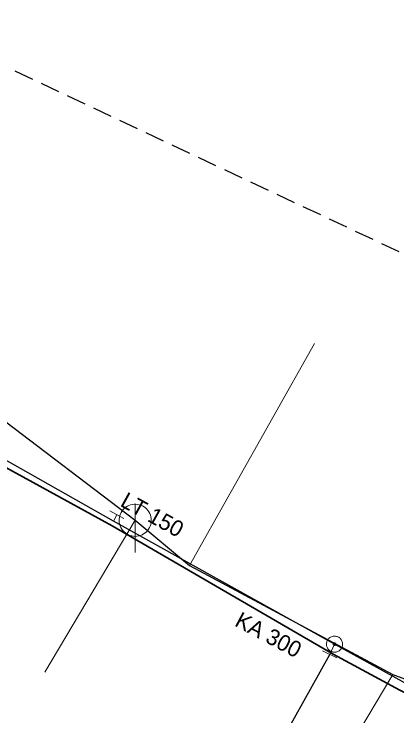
# Model space of a CAD drawing. Extents: x -749365 to -748625, y -965388 to -964881.
# Drawn here: x -749326.21 to -749302.39, y -964927.15 to -964883.5 of the extents above; entities that cross this region are included whole.
import ezdxf

# ---------------------------------------------------------------- set-up
doc = ezdxf.new("R2010")
doc.units = 0
doc.header["$LTSCALE"] = 0.4
doc.linetypes.add('MEDIUM_DASHED', pattern=[4.5, 3, -1.5])
for name, color, linetype, lineweight in [('1', 7, 'MEDIUM_DASHED', 25), ('11', 7, 'Continuous', 13), ('14', 7, 'Continuous', 13), ('17', 7, 'Continuous', 25), ('22', 7, 'Continuous', 13), ('34', 7, 'Continuous', 13), ('47', 7, 'Continuous', 13)]:
    doc.layers.add(name, color=color, linetype=linetype, lineweight=lineweight)

msp = doc.modelspace()

# ---------------------------------------------------------------- linework, layer by layer
at = {"layer": '1'}
msp.add_lwpolyline([(-748913.896, -965162.751), (-749358.2, -964911.234), (-749358.98, -964910.689), (-749359.642, -964910.006), (-749360.163, -964909.209), (-749360.523, -964908.329), (-749360.711, -964907.396), (-749360.718, -964906.445), (-749360.545, -964905.509), (-749360.198, -964904.624), (-749359.689, -964903.82), (-749359.037, -964903.126), (-749338.098, -964884.732), (-749337.314, -964884.168), (-749336.437, -964883.765), (-749335.498, -964883.538), (-749334.533, -964883.496), (-749333.578, -964883.64), (-749332.669, -964883.965), (-749106.184, -964990.559)], dxfattribs=at)
at = {"layer": '11'}
for p, q in [((-749307.528, -964903.991), (-749315.285, -964917.793)), ((-749324.298, -964924.421), (-749318.67, -964914.98)), ((-749313.264, -964942.418), (-749302.649, -964924.581))]:
    msp.add_line(p, q, dxfattribs=at)
at = {"layer": '14', "lineweight": 25}
msp.add_line((-749340.739, -964898.23), (-749318.67, -964914.98), dxfattribs=at)
at = {"layer": '14'}
for p, q in [((-749320.025, -964915.03), (-749319.813, -964914.633)), ((-749306.274, -964922.687), (-749306.572, -964923.32))]:
    msp.add_line(p, q, dxfattribs=at)
at = {"layer": '14', "lineweight": 25}
msp.add_lwpolyline([(-749318.67, -964914.98), (-749315.285, -964917.793), (-749302.649, -964924.581), (-749299.42, -964925.78)], dxfattribs=at)
at = {"layer": '17', "lineweight": 35}
msp.add_lwpolyline([(-749338.07, -964901.664), (-749339.897, -964904.533), (-749328.89, -964910.512), (-749320.106, -964915.328), (-749306.348, -964923.318), (-749302.22, -964925.541), (-749292.258, -964930.514), (-749280.577, -964937.024), (-749272.375, -964941.575), (-749255.349, -964950.855), (-749231.471, -964964.54), (-749222.21, -964969.832), (-749218.876, -964969.25), (-749196.521, -964982.106)], dxfattribs=at)
at = {"layer": '17'}
for points in [[(-749306.274, -964922.687), (-749320.025, -964915.03), (-749328.782, -964910.09)], [(-749278.003, -964937.651), (-749302.022, -964925.022), (-749306.274, -964922.687)], [(-749316.889, -964940.366), (-749310.352, -964930.127), (-749306.572, -964923.32)]]:
    msp.add_lwpolyline(points, dxfattribs=at)
at = {"layer": '22'}
msp.add_line((-749318.67, -964916.98), (-749318.669, -964913.98), dxfattribs=at)
msp.add_lwpolyline([(-749317.67, -964914.98), (-749317.675, -964914.871), (-749317.693, -964914.763), (-749317.723, -964914.657), (-749317.763, -964914.556), (-749317.815, -964914.459), (-749317.877, -964914.369), (-749317.949, -964914.286), (-749318.029, -964914.212), (-749318.117, -964914.146), (-749318.211, -964914.091), (-749318.311, -964914.046), (-749318.416, -964914.013), (-749318.523, -964913.991), (-749318.632, -964913.981), (-749318.742, -964913.983), (-749318.85, -964913.997), (-749318.957, -964914.022), (-749319.06, -964914.059), (-749319.158, -964914.108), (-749319.25, -964914.166), (-749319.336, -964914.235), (-749319.413, -964914.312), (-749319.482, -964914.398), (-749319.541, -964914.49), (-749319.589, -964914.588), (-749319.626, -964914.691), (-749319.652, -964914.798), (-749319.666, -964914.906), (-749319.669, -964915.016), (-749319.659, -964915.125), (-749319.638, -964915.232), (-749319.604, -964915.336), (-749319.56, -964915.436), (-749319.505, -964915.531), (-749319.439, -964915.619), (-749319.365, -964915.699), (-749319.282, -964915.771), (-749319.192, -964915.833), (-749319.096, -964915.885), (-749318.994, -964915.926), (-749318.889, -964915.956), (-749318.781, -964915.974), (-749318.671, -964915.98), (-749318.562, -964915.974), (-749318.454, -964915.956), (-749318.349, -964915.927), (-749318.247, -964915.886), (-749318.15, -964915.834), (-749318.06, -964915.772), (-749317.977, -964915.701), (-749317.902, -964915.621), (-749317.837, -964915.533), (-749317.781, -964915.439), (-749317.737, -964915.339), (-749317.703, -964915.235), (-749317.681, -964915.127), (-749317.671, -964915.018)], close=True, dxfattribs=at)
at = {"layer": '34'}
for p, q in [((-749320.249, -964914.388), (-749319.377, -964914.878)), ((-749306.119, -964923.532), (-749307.024, -964923.106))]:
    msp.add_line(p, q, dxfattribs=at)
at = {"layer": '47'}
for points in [[(-749306.487, -964923.139), (-749306.438, -964923.158), (-749306.388, -964923.173), (-749306.337, -964923.182), (-749306.285, -964923.186), (-749306.232, -964923.185), (-749306.18, -964923.177), (-749306.13, -964923.165), (-749306.08, -964923.147), (-749306.033, -964923.125), (-749305.988, -964923.097), (-749305.947, -964923.065), (-749305.91, -964923.028), (-749305.876, -964922.989), (-749305.846, -964922.945), (-749305.821, -964922.9), (-749305.802, -964922.851), (-749305.787, -964922.801), (-749305.778, -964922.749), (-749305.774, -964922.698), (-749305.775, -964922.645), (-749305.783, -964922.593), (-749305.795, -964922.542), (-749305.813, -964922.492), (-749305.835, -964922.446), (-749305.863, -964922.401), (-749305.895, -964922.36), (-749305.931, -964922.322), (-749305.971, -964922.289), (-749306.015, -964922.259), (-749306.06, -964922.234), (-749306.109, -964922.215), (-749306.159, -964922.2), (-749306.211, -964922.19), (-749306.262, -964922.187), (-749306.315, -964922.188), (-749306.367, -964922.195), (-749306.418, -964922.207), (-749306.467, -964922.225), (-749306.514, -964922.248), (-749306.559, -964922.276), (-749306.6, -964922.308), (-749306.638, -964922.343), (-749306.671, -964922.384), (-749306.701, -964922.428), (-749306.726, -964922.473), (-749306.745, -964922.522), (-749306.76, -964922.572), (-749306.77, -964922.623), (-749306.773, -964922.675), (-749306.772, -964922.728), (-749306.765, -964922.78), (-749306.752, -964922.83), (-749306.735, -964922.879), (-749306.712, -964922.927), (-749306.684, -964922.972), (-749306.652, -964923.013), (-749306.616, -964923.05), (-749306.576, -964923.084), (-749306.532, -964923.114)], [(-749306.308, -964922.761), (-749306.3, -964922.765), (-749306.292, -964922.766), (-749306.284, -964922.768), (-749306.276, -964922.768), (-749306.267, -964922.768), (-749306.258, -964922.767), (-749306.25, -964922.765), (-749306.242, -964922.762), (-749306.234, -964922.758), (-749306.227, -964922.754), (-749306.22, -964922.748), (-749306.214, -964922.742), (-749306.208, -964922.736), (-749306.203, -964922.73), (-749306.199, -964922.721), (-749306.195, -964922.713), (-749306.194, -964922.705), (-749306.192, -964922.697), (-749306.192, -964922.689), (-749306.192, -964922.68), (-749306.193, -964922.671), (-749306.195, -964922.663), (-749306.198, -964922.655), (-749306.202, -964922.646), (-749306.206, -964922.64), (-749306.212, -964922.633), (-749306.218, -964922.627), (-749306.224, -964922.621), (-749306.23, -964922.616), (-749306.239, -964922.612), (-749306.247, -964922.608), (-749306.255, -964922.607), (-749306.263, -964922.605), (-749306.271, -964922.605), (-749306.28, -964922.605), (-749306.288, -964922.605), (-749306.297, -964922.608), (-749306.305, -964922.611), (-749306.314, -964922.615), (-749306.32, -964922.619), (-749306.327, -964922.625), (-749306.333, -964922.631), (-749306.339, -964922.637), (-749306.344, -964922.643), (-749306.348, -964922.652), (-749306.352, -964922.66), (-749306.353, -964922.668), (-749306.355, -964922.676), (-749306.355, -964922.684), (-749306.355, -964922.693), (-749306.355, -964922.701), (-749306.352, -964922.71), (-749306.349, -964922.718), (-749306.345, -964922.726), (-749306.341, -964922.733), (-749306.335, -964922.74), (-749306.329, -964922.746), (-749306.323, -964922.752), (-749306.317, -964922.757)]]:
    msp.add_lwpolyline(points, close=True, dxfattribs=at)

# ---------------------------------------------------------------- texts
at = {"layer": '1'}
for s, rotation, p in [('LT 150', 331, (-749319.664, -964914.063)), ('KA 300', 332, (-749312.548, -964921.515))]:
    msp.add_text(s, height=1, rotation=rotation, dxfattribs=at).set_placement(p)

doc.saveas('drawing.dxf')
